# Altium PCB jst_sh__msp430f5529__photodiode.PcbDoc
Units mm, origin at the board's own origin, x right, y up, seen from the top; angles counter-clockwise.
Board outline 62 x 34 mm, 2 copper layers (Top, Bottom), stack 0 mm thick; 21 components, 14 nets, 133 pads, 39 vias.
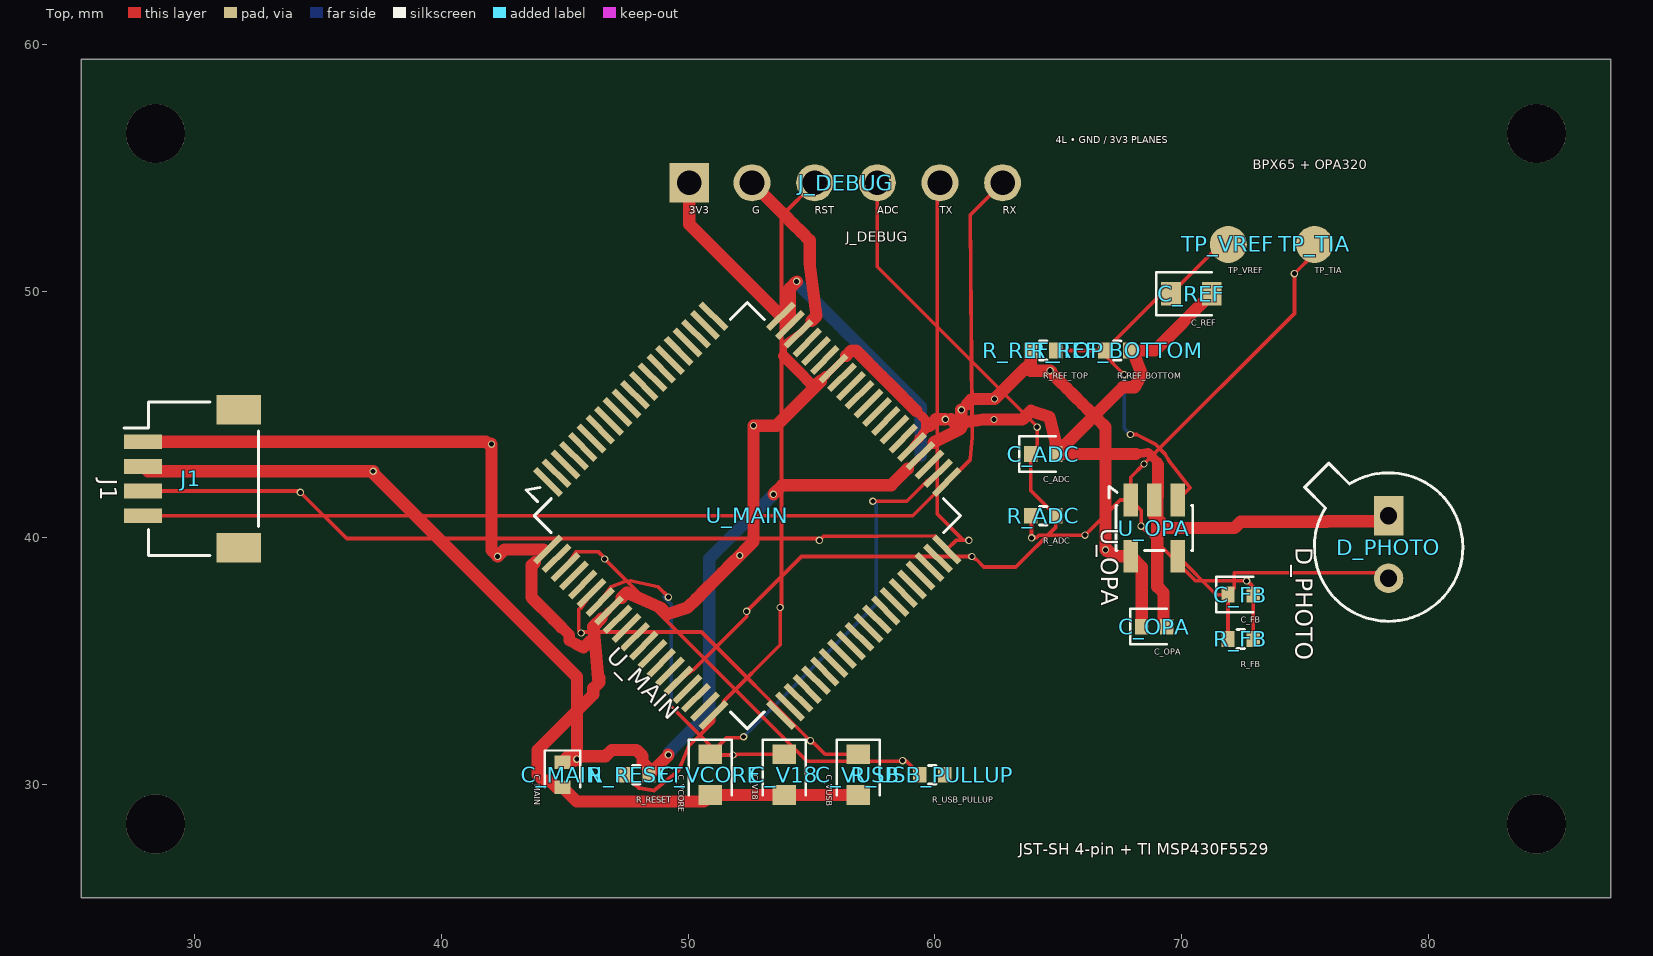
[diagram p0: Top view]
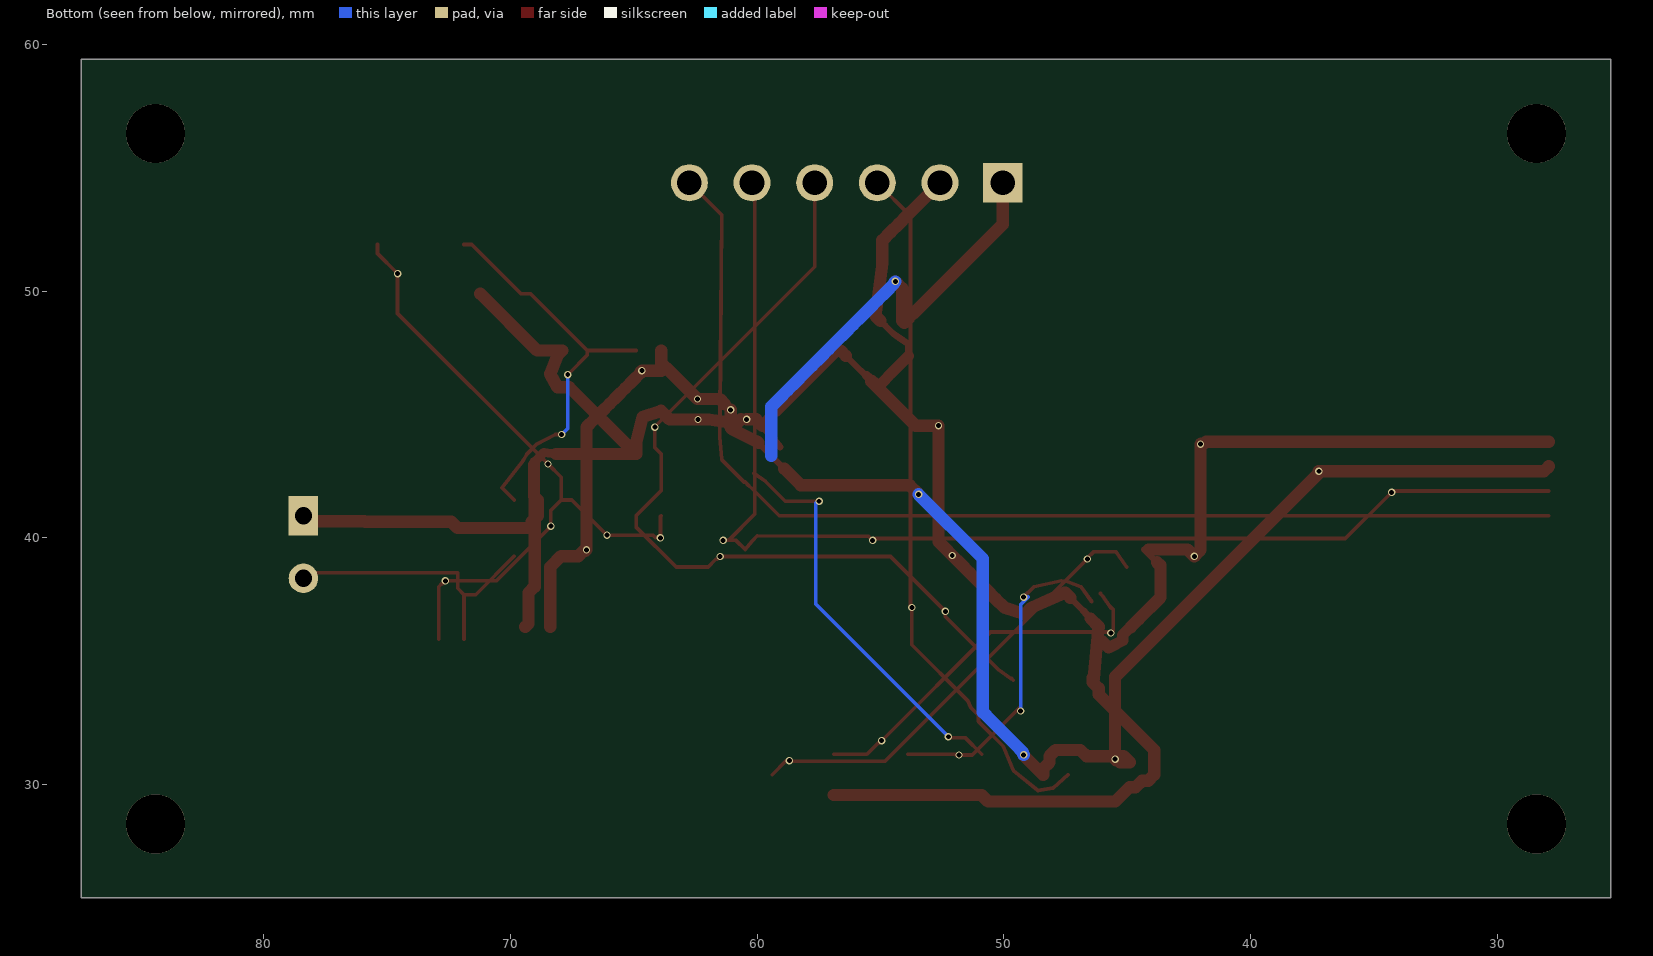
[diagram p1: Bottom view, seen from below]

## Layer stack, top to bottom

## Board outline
25.4,59.4 87.4,59.4 87.4,25.4 25.4,25.4

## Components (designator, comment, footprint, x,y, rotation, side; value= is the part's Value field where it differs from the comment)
C_ADC "" TSCIRCUIT-1.5600x0.6400mm 64.4,43.4 r0 top
C_FB "" TSCIRCUIT-1.5600x0.6400mm 72.4,37.7 r0 top
C_MAIN "" TSCIRCUIT-0.6400x1.5600mm 44.9,30.4 r270 top
C_OPA "" TSCIRCUIT-1.5600x0.6400mm 68.9,36.4 r0 top
C_REF "" TSCIRCUIT-2.4500x0.9500mm 70.4,49.9 r0 top
C_V18 "" TSCIRCUIT-0.9500x2.4500mm 53.9,30.4 r270 top
C_VCORE "" TSCIRCUIT-0.9500x2.4500mm 50.9,30.4 r270 top
C_VUSB "" TSCIRCUIT-0.9500x2.4500mm 56.9,30.4 r270 top
D_PHOTO "" TSCIRCUIT-1.2000x3.9400mm 78.4,39.73 r270 top
J1 "" TSCIRCUIT-5.5500x6.8000mm 29.9,42.4 r270 top
J_DEBUG "" TSCIRCUIT-14.2000x1.5000mm 56.4,54.4 r0 top
R_ADC "" TSCIRCUIT-1.5600x0.6400mm 64.4,40.9 r0 top
R_FB "" TSCIRCUIT-1.5600x0.6400mm 72.4,35.9 r0 top
R_REF_BOTTOM "" TSCIRCUIT-1.5600x0.6400mm 67.4,47.6 r0 top
R_REF_TOP "" TSCIRCUIT-1.5600x0.6400mm 64.4,47.6 r0 top
R_RESET "" TSCIRCUIT-1.5600x0.6400mm 47.9,30.4 r0 top
R_USB_PULLUP "" TSCIRCUIT-1.5600x0.6400mm 59.9,30.4 r0 top
TP_TIA "" TSCIRCUIT-1.5000x1.5000mm 75.4,51.9 r0 top
TP_VREF "" TSCIRCUIT-1.5000x1.5000mm 71.9,51.9 r0 top
U_MAIN "" TSCIRCUIT-17.3948x17.3948mm 52.4,40.9 r315 top
U_OPA "" TSCIRCUIT-2.5000x3.6000mm 68.9,40.4 r270 top

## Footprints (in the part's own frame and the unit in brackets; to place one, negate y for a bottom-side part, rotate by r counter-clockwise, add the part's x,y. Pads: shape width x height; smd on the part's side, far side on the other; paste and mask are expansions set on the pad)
TSCIRCUIT-0.6400x1.5600mm [mm]
  rect 0.54x0.64 smd: 1(-0.51,0) 2(0.51,0)
  silkscreen extent -0.98,-0.72 0.51,0.72
TSCIRCUIT-0.9500x2.4500mm [mm]
  rect 0.8x0.95 smd: 1(-0.825,0) 2(0.825,0)
  silkscreen extent -1.43,-0.87 0.82,0.88
TSCIRCUIT-1.2000x3.9400mm [mm]
  rect 1.6x1.2 hole 0.7: 1(-1.17,0)
  round 1.2 hole 0.7: 2(1.37,0)
  silkscreen extent -3.3,-3.4 3.11,3.01
TSCIRCUIT-1.5000x1.5000mm [mm]
  round 1.5 smd: 1(0,0)
TSCIRCUIT-1.5600x0.6400mm [mm]
  rect 0.54x0.64 smd: 1(-0.51,0) 2(0.51,0)
  silkscreen extent -0.98,-0.72 0.51,0.72
TSCIRCUIT-2.4500x0.9500mm [mm]
  rect 0.8x0.95 smd: 1(-0.825,0) 2(0.825,0)
  silkscreen extent -1.42,-0.87 0.83,0.87
TSCIRCUIT-2.5000x3.6000mm [mm]
  rect 1.325x0.6 smd: 1(-1.137,-0.95) 2(-1.137,0) 3(-1.137,0.95) 4(1.138,0.95) 5(1.138,-0.95)
  silkscreen extent -1.69,-1.84 0.91,1.56
TSCIRCUIT-5.5500x6.8000mm [mm]
  rect 1.2x1.8 smd: 1(-2.8,1.875) 1(2.8,1.875)
  rect 0.6x1.55 smd: 1(-1.5,-2) 2(-0.5,-2) 3(0.5,-2) 4(1.5,-2)
  silkscreen extent -3.11,-2.78 3.11,2.68
TSCIRCUIT-14.2000x1.5000mm [mm]
  rect 1.6x1.6 hole 1: 1(-6.35,0)
  round 1.5 hole 1: 2(-3.81,0) 3(-1.27,0) 4(1.27,0) 5(3.81,0) 6(6.35,0)
TSCIRCUIT-17.3948x17.3948mm [mm]
  rect 1.475x0.25 smd: 1(-6.687,-4.75) 2(-6.687,-4.25) 3(-6.687,-3.75) 4(-6.687,-3.25) 5(-6.687,-2.75) 6(-6.687,-2.25) 7(-6.687,-1.75) 8(-6.687,-1.25) 9(-6.687,-0.75) 10(-6.687,-0.25) 11(-6.687,0.25) 12(-6.687,0.75) 13(-6.687,1.25) 14(-6.687,1.75) 15(-6.687,2.25) 16(-6.687,2.75) 17(-6.687,3.25) 18(-6.687,3.75) 19(-6.687,4.25) 20(-6.687,4.75) 41(6.688,4.75) 42(6.687,4.25) 43(6.687,3.75) 44(6.687,3.25) 45(6.688,2.75) 46(6.687,2.25) 47(6.687,1.75) 48(6.687,1.25) 49(6.687,0.75) 50(6.687,0.25) 51(6.687,-0.25) 52(6.687,-0.75) 53(6.687,-1.25) 54(6.687,-1.75) 55(6.687,-2.25) 56(6.687,-2.75) 57(6.687,-3.25) 58(6.687,-3.75) 59(6.687,-4.25) 60(6.687,-4.75)
  rect 0.25x1.475 smd: 21(-4.75,6.688) 22(-4.25,6.687) 23(-3.75,6.687) 24(-3.25,6.688) 25(-2.75,6.688) 26(-2.25,6.687) 27(-1.75,6.687) 28(-1.25,6.688) 29(-0.75,6.688) 30(-0.25,6.687) 31(0.25,6.687) 32(0.75,6.688) 33(1.25,6.688) 34(1.75,6.687) 35(2.25,6.687) 36(2.75,6.688) 37(3.25,6.688) 38(3.75,6.687) 39(4.25,6.687) 40(4.75,6.688) 61(4.75,-6.687) 62(4.25,-6.687) 63(3.75,-6.687) 64(3.25,-6.687) 65(2.75,-6.687) 66(2.25,-6.687) 67(1.75,-6.687) 68(1.25,-6.687) 69(0.75,-6.687) 70(0.25,-6.687) 71(-0.25,-6.687) 72(-0.75,-6.687) 73(-1.25,-6.687) 74(-1.75,-6.687) 75(-2.25,-6.687) 76(-2.75,-6.687) 77(-3.25,-6.687) 78(-3.75,-6.687) 79(-4.25,-6.687) 80(-4.75,-6.687)
  silkscreen extent -7.09,-6.11 6.11,6.11

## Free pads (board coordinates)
  round 2.4 hole 2.4 unplated: NPTH-1(28.4,28.4) NPTH-2(84.4,56.4) NPTH-3(84.4,28.4) NPTH-4(28.4,56.4)

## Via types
v1: diameter 0.3, hole 0.2, Top to Bottom, 39 vias

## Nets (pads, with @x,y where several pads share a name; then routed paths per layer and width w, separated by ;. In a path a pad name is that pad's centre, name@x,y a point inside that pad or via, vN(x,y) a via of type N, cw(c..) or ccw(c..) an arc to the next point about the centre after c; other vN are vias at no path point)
ADC_IN: C_ADC.1 J_DEBUG.4 R_ADC.2 U_MAIN.65 | length 35.5
  Top w0.15: U_MAIN.65 49.691,34.302 49.722,34.302 50.226,34.66 50.215,34.652 52.37,36.807 v1(52.37,37.02) 52.411,37.061 54.598,39.248 v1(61.503,39.248) 61.618,39.133 61.68,39.133 61.99,38.823 63.287,38.823 64.91,40.446 R_ADC.2 63.89,41.92 C_ADC.1 64.152,43.662 v1(64.152,44.489) 64.134,44.507 64.134,44.528 57.67,50.991 J_DEBUG.4
GND: C_ADC.2 C_MAIN.2 C_OPA.2 C_REF.2 C_V18.2 C_VCORE.2 C_VUSB.2 D_PHOTO.1 J1.1@27.9,43.9 J_DEBUG.2 R_REF_BOTTOM.2 U_MAIN.23 U_MAIN.27 U_MAIN.36 U_MAIN.73 U_MAIN.80 U_OPA.2 | length 124.4
  Top w0.25: U_MAIN.80@43.791,39.008 U_MAIN.80 44.136,39.53 ; U_MAIN.73@46.273,36.526 U_MAIN.73 U_MAIN.73@47.309,37.577 ; U_MAIN.23 54.8,48.6 U_MAIN.23@55,48.8 ; U_MAIN.27@55.37,46.345 U_MAIN.27 ; U_MAIN.27@55.571,46.588 U_MAIN.27 ; U_MAIN.27@56.413,47.388 U_MAIN.27 ; U_MAIN.36 U_MAIN.36@59.4,44 ; U_MAIN.36@59.302,43.989 59.302,44.062 U_MAIN.36@59.52,44.28
  Top w0.275: 53.867,47.376 53.867,47.849 53.867,47.85 53.867,47.847 54.172,48.064 U_MAIN.23 ; U_MAIN.36 U_MAIN.36@59.302,43.989 ; U_MAIN.36@59.4,44 59.6,44.4 ; v1(60.426,44.805) v1@60.43,44.809
  Top w0.296: U_MAIN.73@46.49,36.738 U_MAIN.73
  Top w0.3: 59.6,44.4 59.6,44.6 ; v1@60.43,44.809 60.655,44.809
  Top w0.325: 59.52,44.28 59.784,44.544 ; 59.6,44.6 59.6,44.8
  Top w0.353: U_MAIN.27@55.333,46.381 U_MAIN.27@55.571,46.588
  Top w0.375: 59.25,45.15 59.6,44.8 ; 68.158,43.4 68.65,43.462 68.838,43.275 69.025,43.088
  Top w0.4: 69.025,43.088 69.049,42.973
  Top w0.437: 55.087,46.119 55.25,46.309 U_MAIN.27@55.333,46.381
  Top w0.45: 44.856,36.382 45.179,36.059 45.171,35.838 45.463,35.692 ; 53.867,47.376 54.108,47.135 54.349,46.893 54.591,46.652 54.839,46.385 55.087,46.119
  Top w0.475: 45.463,35.692 45.754,35.546 45.973,35.765 46.192,35.983 46.192,36.421 U_MAIN.73@46.49,36.738
  Top w0.5: J1.1@27.9,43.9 28.396,43.9 28.893,43.9 29.389,43.9 29.885,43.9 30.381,43.9 30.878,43.9 31.374,43.9 31.87,43.9 32.367,43.9 32.863,43.9 33.359,43.9 33.856,43.9 34.352,43.9 34.848,43.9 35.344,43.9 35.841,43.9 36.337,43.9 36.833,43.9 37.33,43.9 37.826,43.9 38.322,43.9 38.818,43.9 39.315,43.9 39.811,43.9 40.307,43.9 40.804,43.9 41.3,43.9 41.796,43.9 41.869,43.827 42.003,43.827 v1(42.027,43.803) 42.027,43.326 42.027,42.849 42.027,42.372 42.027,41.895 42.027,41.418 42.027,40.941 42.027,40.464 42.027,39.987 42.027,39.51 42.219,39.319 42.219,39.306 v1(42.275,39.25) 42.555,39.53 42.994,39.53 43.434,39.53 43.873,39.53 44.136,39.53 ; U_MAIN.80@43.791,39.008 43.682,38.9 43.65,38.9 43.65,37.588 44.532,36.706 44.856,36.382 ; 46.273,36.526 46.15,36.4 46.2,36 46.355,34.282 46.4,34.327 46.4,34.15 46.15,33.9 46.15,33.65 43.9,31.4 43.9,30.4 44.15,30.15 44.4,30.15 44.66,29.89 C_MAIN.2 45.48,29.31 50.635,29.31 C_VCORE.2 C_V18.2 C_VUSB.2 ; U_MAIN.73@47.309,37.577 47.507,37.775 47.525,37.775 48.871,37.178 49.15,36.9 ; 49.15,36.9 49.98,37.178 50.332,37.53 50.684,37.882 51.036,38.234 51.387,38.585 51.739,38.937 v1(52.091,39.289) 52.37,39.568 52.649,39.847 52.649,40.318 52.649,40.788 52.649,41.259 52.649,41.73 52.649,42.2 52.649,42.671 52.649,43.142 52.649,43.613 52.649,44.083 v1(52.649,44.554) 53.579,44.554 U_MAIN.27@55.37,46.345 ; J_DEBUG.2 52.923,54.067 53.257,53.733 53.59,53.4 53.923,53.067 54.257,52.733 54.59,52.4 54.924,52.066 54.924,51.61 54.924,51.153 55.2,49 55,48.8 ; 56.413,47.388 56.625,47.6 56.8,47.6 57.15,47.25 57.5,46.9 57.85,46.55 58.2,46.2 58.55,45.85 58.9,45.5 59.25,45.15 ; 59.784,44.544 60.045,44.805 v1(60.426,44.805) ; 60.655,44.809 60.664,44.8 60.814,44.65 60.9,44.65 61.966,44.8 v1(62.4,44.8) 63.55,44.8 63.9,45.15 64.65,44.9 64.91,43.829 C_ADC.2 ; 68.158,43.4 67.694,43.4 67.23,43.4 66.766,43.4 66.302,43.4 65.838,43.4 65.374,43.4 C_ADC.2 ; 69.049,42.973 69.049,41.686 U_OPA.2 ; C_OPA.2 69.4,36.4 69.275,36.525 69.275,37.775 69.025,38.025 69.025,41.525 68.913,41.525 U_OPA.2 ; C_REF.2 68.925,47.6 R_REF_BOTTOM.2 68.095,47.415 68.4,46.65 68.095,46.111 67.621,46.111 C_ADC.2 ; D_PHOTO.1 78.181,40.681 77.685,40.681 77.189,40.681 76.692,40.681 76.196,40.681 75.931,40.681 75.9,40.65 72.4,40.65 72.15,40.4 69.15,40.4 69.15,40.65 68.9,40.9 U_OPA.2
MAIN_RESET: J_DEBUG.3 R_RESET.1 U_MAIN.61 | length 28.7
  Top w0.15: R_RESET.1 48.004,29.862 48.615,29.761 49.617,30.578 50.021,31.552 51.03,32.561 U_MAIN.61 51.335,33.117 51.47,33.403 53.731,35.664 v1(53.731,37.177) 53.783,37.229 53.783,37.458 53.783,53.053 J_DEBUG.3
MSP_USB_PUR: R_USB_PULLUP.1 U_MAIN.78 | length 18.5
  Top w0.15: U_MAIN.78 45.453,39.433 45.454,39.434 46.369,39.434 46.606,39.198 46.606,39.154 v1(46.614,39.146) 54.814,30.946 58.694,30.946 v1(58.694,30.97) 58.82,30.97 R_USB_PULLUP.1
MSP_V18: C_V18.1 U_MAIN.74 | length 13.8
  Top w0.15: U_MAIN.74 46.867,38.019 46.878,38.021 47.403,38.217 47.666,38.267 48.779,38.021 v1(49.2,37.6) ; v1(49.316,32.982) 49.363,33.029 49.363,33.112 51.279,31.196 v1(51.818,31.196) 51.838,31.176 51.92,31.176 51.969,31.225 C_V18.1
  Bottom w0.15: v1(49.2,37.6) 49.197,37.603 49.01,37.603 49.316,37.297 v1(49.316,32.982)
MSP_VCORE: C_VCORE.1 U_MAIN.39 | length 16.6
  Top w0.15: C_VCORE.1 51.578,31.903 52.119,31.903 52.212,31.903 v1(52.246,31.937) ; v1(57.489,41.488) 58.859,41.488 59.652,42.281 U_MAIN.39
  Bottom w0.15: v1(52.246,31.937) 57.622,37.313 57.622,41.432 57.545,41.432 v1(57.489,41.488)
MSP_VUSB: C_VUSB.1 U_MAIN.75 | length 15.4
  Top w0.15: U_MAIN.75 46.08,37.732 46.006,37.658 45.647,37.152 45.719,37.253 45.568,37.102 45.568,36.235 v1(45.657,36.146) 45.7,36.189 45.782,36.189 50.544,36.189 v1(54.954,31.779) 55.046,31.687 55.091,31.687 55.553,31.225 C_VUSB.1
PD_SUM: C_FB.1 D_PHOTO.2 R_FB.1 U_OPA.4 | length 11.8
  Top w0.15: U_OPA.4 71.412,37.7 C_FB.1 ; R_FB.1 C_FB.1 ; D_PHOTO.2 78.167,38.593 72.147,38.593 72.147,37.957 C_FB.1
TIA_OUT: C_FB.2 R_ADC.1 R_FB.2 TP_TIA.1 U_OPA.1 | length 27.9
  Top w0.15: R_ADC.1 63.925,40.865 v1(63.925,39.999) 63.942,40.016 64.129,40.016 64.224,40.111 v1(66.089,40.111) 66.108,40.13 67.516,41.537 U_OPA.1 ; R_FB.2 C_FB.2 72.91,38.02 72.782,38.147 72.754,38.147 v1(72.643,38.258) 70.584,38.258 68.375,40.466 v1(68.367,40.475) 68.367,41.12 U_OPA.1 ; TP_TIA.1 75.4,51.536 74.597,50.733 v1(74.583,50.719) 74.583,49.098 68.529,43.044 v1(68.482,42.996) 67.95,42.465 U_OPA.1
UART_MAIN_RX: J1.4 J_DEBUG.6 U_MAIN.40 | length 46.3
  Top w0.15: J1.4 59.11,40.9 60.162,41.951 60.183,41.975 60.364,42.136 60.348,42.124 60.348,42.13 U_MAIN.40 60.538,42.27 60.679,42.411 61.432,43.164 61.432,43.196 61.52,44.091 61.509,44.986 61.432,53.082 J_DEBUG.6
UART_MAIN_TX: J1.3 J_DEBUG.5 U_MAIN.41 | length 50
  Top w0.15: J1.3 34.15,41.9 34.225,41.9 v1(34.275,41.85) 36.152,39.973 55.245,39.973 v1(55.318,39.9) 55.473,40.055 59.994,40.087 60.215,39.867 U_MAIN.41 60.858,39.9 v1(61.383,39.9) 61.168,39.9 60.101,40.967 60.101,41.195 60.101,54.291 J_DEBUG.5
USB_DP_MCU: R_USB_PULLUP.2
VCC_3V3: C_MAIN.1 C_OPA.1 J1.2 J_DEBUG.1 R_REF_TOP.1 R_RESET.2 U_MAIN.21 U_MAIN.22 U_MAIN.37 U_OPA.5 | length 89
  Top w0.25: U_MAIN.21@53.682,49.076 U_MAIN.21 53.858,48.899 ; 54.035,48.722 U_MAIN.22 54.124,48.811 ; U_MAIN.37@58.905,42.809 U_MAIN.37 U_MAIN.37@59.948,43.852
  Top w0.325: v1(61.077,45.194) v1@61.096,45.213
  Top w0.35: v1@61.096,45.213 61.305,45.422
  Top w0.5: J1.2 28.097,42.703 v1(37.227,42.703) 37.243,42.687 37.243,42.612 45.49,34.365 v1(45.49,31.029) 45.451,30.99 45.367,30.99 45.287,30.91 C_MAIN.1 44.91,30.91 45.15,31.15 46.65,31.15 46.9,31.4 47.9,31.4 48.15,31.15 48.15,30.9 48.4,30.65 48.4,30.4 R_RESET.2 48.673,30.663 48.936,30.926 49.199,31.189 v1(49.199,31.203) ; J_DEBUG.1 50.05,52.708 53.682,49.076 ; v1(53.458,41.764) 53.458,41.773 53.82,42.136 58.232,42.136 58.905,42.809 ; 53.858,48.899 54.035,48.722 ; 54.124,48.811 54.124,49.131 54.124,49.627 54.124,50.124 v1(54.4,50.4) ; U_MAIN.37@59.948,43.852 59.996,43.9 60.025,43.9 61,44.4 61.077,44.477 v1(61.077,45.194) ; 61.305,45.422 61.514,45.631 61.967,45.631 v1(62.42,45.631) 62.499,45.71 62.847,46.058 63.195,46.406 63.542,46.753 63.89,47.101 R_REF_TOP.1 63.89,46.78 v1(64.675,46.78) 64.72,46.735 64.72,46.698 65.035,46.384 65.349,46.07 65.664,45.755 65.978,45.441 66.292,45.127 66.607,44.812 66.921,44.498 66.921,44 66.921,43.502 66.921,43.004 66.921,42.506 66.921,42.008 66.921,41.51 66.921,41.012 66.921,40.514 66.921,40.016 v1(66.921,39.518) 66.962,39.477 67.039,39.477 67.254,39.262 67.602,39.262 U_OPA.5 68.39,38.823 C_OPA.1
  Bottom w0.5: v1(49.199,31.203) 49.221,31.225 49.221,31.306 49.547,31.632 49.873,31.957 50.198,32.283 50.524,32.609 50.85,32.934 50.85,39.156 v1(53.458,41.764) ; v1(54.4,50.4) 54.451,50.349 54.451,50.304 54.783,49.972 55.115,49.64 55.446,49.309 55.778,48.977 56.11,48.645 56.441,48.313 56.773,47.982 57.105,47.65 57.437,47.318 57.768,46.987 58.1,46.655 58.432,46.323 58.763,45.991 59.095,45.66 59.427,45.328 59.427,44.829 59.427,44.329 59.427,43.83 59.427,43.331
VREF_0V5: C_REF.1 R_REF_BOTTOM.1 R_REF_TOP.2 TP_VREF.1 U_OPA.3 | length 16.7
  Top w0.15: R_REF_TOP.2 R_REF_BOTTOM.1 ; v1(67.683,46.622) 67.626,46.679 66.89,47.415 R_REF_BOTTOM.1 ; v1(67.929,44.192) 68.184,44.192 68.949,43.799 69.335,43.403 69.481,43.157 70.345,42.032 U_OPA.3 ; TP_VREF.1 71.575,51.9 C_REF.1 69.19,49.9 R_REF_BOTTOM.1
  Bottom w0.15: v1(67.683,46.622) 67.683,44.438 67.905,44.216 v1(67.929,44.192)
pads on no net: J1.1@31.775,39.6 J1.1@31.775,45.2 U_MAIN.1 U_MAIN.2 U_MAIN.3 U_MAIN.4 U_MAIN.5 U_MAIN.6 U_MAIN.7 U_MAIN.8 U_MAIN.9 U_MAIN.10 U_MAIN.11 U_MAIN.12 U_MAIN.13 U_MAIN.14 U_MAIN.15 U_MAIN.16 U_MAIN.17 U_MAIN.18 U_MAIN.19 U_MAIN.20 U_MAIN.24 U_MAIN.25 U_MAIN.26 U_MAIN.28 U_MAIN.29 U_MAIN.30 U_MAIN.31 U_MAIN.32 U_MAIN.33 U_MAIN.34 U_MAIN.35 U_MAIN.38 U_MAIN.42 U_MAIN.43 U_MAIN.44 U_MAIN.45 U_MAIN.46 U_MAIN.47 U_MAIN.48 U_MAIN.49 U_MAIN.50 U_MAIN.51 U_MAIN.52 U_MAIN.53 U_MAIN.54 U_MAIN.55 U_MAIN.56 U_MAIN.57 U_MAIN.58 U_MAIN.59 U_MAIN.60 U_MAIN.62 U_MAIN.63 U_MAIN.64 U_MAIN.66 U_MAIN.67 U_MAIN.68 U_MAIN.69 U_MAIN.70 U_MAIN.71 U_MAIN.72 U_MAIN.76 U_MAIN.77 U_MAIN.79

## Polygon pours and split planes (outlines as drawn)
GND on Mid1 (solid): 87.1,59.1 25.7,59.1 25.7,25.7 87.1,25.7
VCC_3V3 on Mid2 (solid): 87.1,59.1 25.7,59.1 25.7,25.7 87.1,25.7

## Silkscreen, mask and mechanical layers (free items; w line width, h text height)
Top Overlay:
  text "4L • GND / 3V3 PLANES" at 64.9,55.9 h0.48
  text "BPX65 + OPA320" at 72.9,54.8 h0.65
  text "JST-SH 4-pin + TI MSP430F5529" at 63.4,27 h0.78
